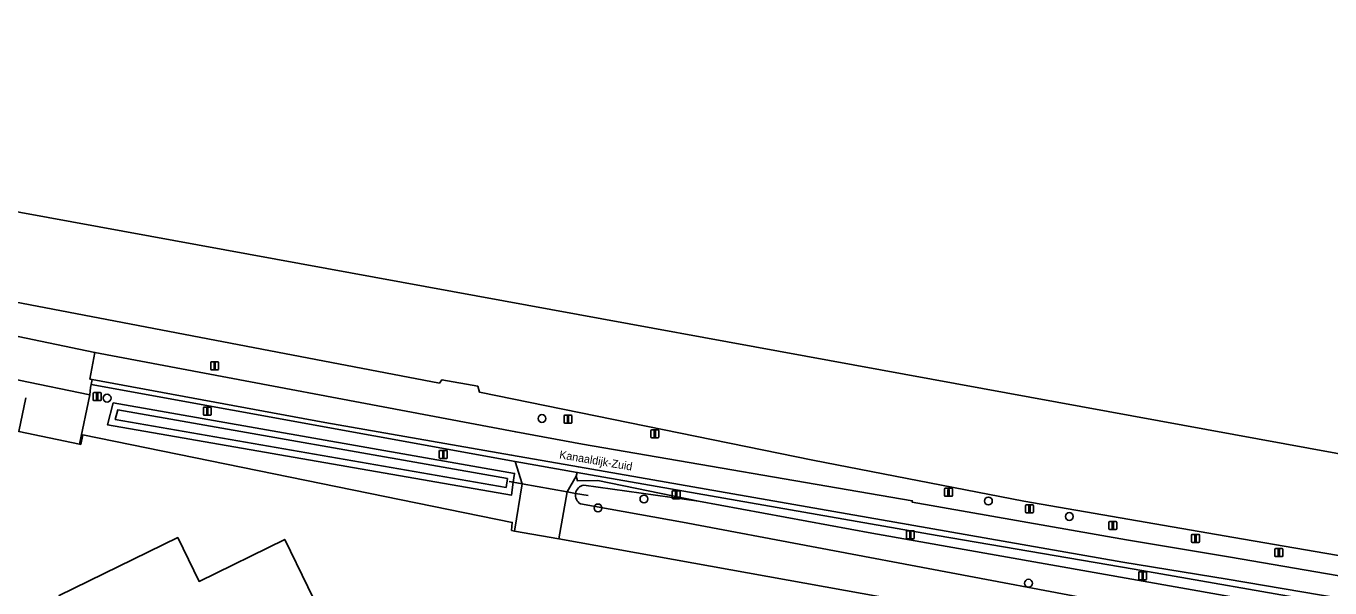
# Model space of a CAD drawing. Extents: x 163043 to 165076, y 382019 to 382874.
# Drawn here: x 163253.6 to 163416.5, y 382804 to 382874.2 of the extents above; entities that cross this region are included whole.
import ezdxf

# ---------------------------------------------------------------- set-up
doc = ezdxf.new("R2010")
doc.units = 0
for name, color, linetype in [('IMGEO_Afsluitpaal', 7, 'Continuous'), ('IMGEO_Boom', 7, 'Continuous'), ('IMGEO_Duiker', 7, 'Continuous'), ('IMGEO_Erf', 7, 'Continuous'), ('IMGEO_Fietspad_gesloten', 7, 'Continuous'), ('IMGEO_Groenvoorziening', 7, 'Continuous'), ('IMGEO_Hek', 7, 'Continuous'), ('IMGEO_Lichtmast', 7, 'Continuous'), ('IMGEO_Oever', 7, 'Continuous'), ('IMGEO_Openbare_ruimte_label', 7, 'Continuous'), ('IMGEO_Pand', 7, 'Continuous'), ('IMGEO_Rijbaan_lokaal_halfverhard', 7, 'Continuous'), ('IMGEO_Rijbaan_lokaal_open', 7, 'Continuous'), ('IMGEO_Verkeersbordpaal', 7, 'Continuous'), ('IMGEO_Voetpad_open', 7, 'Continuous'), ('IMGEO_Waterloop', 7, 'Continuous')]:
    doc.layers.add(name, color=color, linetype=linetype)

msp = doc.modelspace()

# ---------------------------------------------------------------- linework, layer by layer
at = {"layer": 'IMGEO_Afsluitpaal'}
for p, q in [((163320.83, 382824.69), (163320.83, 382825.49)), ((163320.83, 382825.49), (163320.83, 382824.69)), ((163320.93, 382825.59), (163321.72, 382825.59)), ((163321.72, 382825.59), (163320.93, 382825.59)), ((163321.72, 382824.59), (163320.93, 382824.59)), ((163320.93, 382824.59), (163321.72, 382824.59)), ((163321.82, 382825.49), (163321.82, 382824.69)), ((163321.82, 382824.69), (163321.82, 382825.49)), ((163331.68, 382822.85), (163331.68, 382823.65)), ((163331.68, 382823.65), (163331.68, 382822.85)), ((163331.78, 382823.75), (163332.57, 382823.75)), ((163332.57, 382823.75), (163331.78, 382823.75)), ((163332.57, 382822.75), (163331.78, 382822.75)), ((163331.78, 382822.75), (163332.57, 382822.75)), ((163332.67, 382823.65), (163332.67, 382822.85)), ((163332.67, 382822.85), (163332.67, 382823.65)), ((163368.38, 382815.54), (163368.38, 382816.34)), ((163368.38, 382816.34), (163368.38, 382815.54)), ((163368.48, 382816.44), (163369.27, 382816.44)), ((163369.27, 382816.44), (163368.48, 382816.44)), ((163369.37, 382816.34), (163369.37, 382815.54)), ((163369.37, 382815.54), (163369.37, 382816.34)), ((163369.27, 382815.44), (163368.48, 382815.44)), ((163368.48, 382815.44), (163369.27, 382815.44)), ((163378.5, 382813.47), (163378.5, 382814.27)), ((163378.5, 382814.27), (163378.5, 382813.47)), ((163378.6, 382814.37), (163379.39, 382814.37)), ((163379.39, 382814.37), (163378.6, 382814.37)), ((163379.49, 382814.27), (163379.49, 382813.47)), ((163379.49, 382813.47), (163379.49, 382814.27)), ((163379.39, 382813.37), (163378.6, 382813.37)), ((163378.6, 382813.37), (163379.39, 382813.37)), ((163388.91, 382811.4), (163388.91, 382812.2)), ((163388.91, 382812.2), (163388.91, 382811.4)), ((163389.01, 382812.3), (163389.8, 382812.3)), ((163389.8, 382812.3), (163389.01, 382812.3)), ((163389.8, 382811.3), (163389.01, 382811.3)), ((163389.01, 382811.3), (163389.8, 382811.3)), ((163389.9, 382812.2), (163389.9, 382811.4)), ((163389.9, 382811.4), (163389.9, 382812.2)), ((163399.25, 382809.78), (163399.25, 382810.58)), ((163399.25, 382810.58), (163399.25, 382809.78)), ((163399.35, 382810.68), (163400.14, 382810.68)), ((163400.14, 382810.68), (163399.35, 382810.68)), ((163400.14, 382809.68), (163399.35, 382809.68)), ((163399.35, 382809.68), (163400.14, 382809.68)), ((163400.24, 382810.58), (163400.24, 382809.78)), ((163400.24, 382809.78), (163400.24, 382810.58)), ((163409.66, 382808.01), (163409.66, 382808.8)), ((163409.66, 382808.8), (163409.66, 382808.01)), ((163409.76, 382808.9), (163410.55, 382808.9)), ((163410.55, 382808.9), (163409.76, 382808.9)), ((163410.55, 382807.91), (163409.76, 382807.91)), ((163409.76, 382807.91), (163410.55, 382807.91)), ((163410.65, 382808.8), (163410.65, 382808.01)), ((163410.65, 382808.01), (163410.65, 382808.8))]:
    msp.add_line(p, q, dxfattribs=at)
for points in [[(163321.25, 382825.47), (163321.4, 382825.47), (163321.4, 382824.72), (163321.25, 382824.72), (163321.25, 382825.47)], [(163332.1, 382823.62), (163332.25, 382823.62), (163332.25, 382822.87), (163332.1, 382822.87), (163332.1, 382823.62)], [(163368.8, 382816.31), (163368.95, 382816.31), (163368.95, 382815.56), (163368.8, 382815.56), (163368.8, 382816.31)], [(163378.92, 382814.24), (163379.07, 382814.24), (163379.07, 382813.49), (163378.92, 382813.49), (163378.92, 382814.24)], [(163389.33, 382812.18), (163389.48, 382812.18), (163389.48, 382811.43), (163389.33, 382811.43), (163389.33, 382812.18)], [(163399.67, 382810.55), (163399.82, 382810.55), (163399.82, 382809.8), (163399.67, 382809.8), (163399.67, 382810.55)], [(163410.08, 382808.78), (163410.23, 382808.78), (163410.23, 382808.03), (163410.08, 382808.03), (163410.08, 382808.78)]]:
    msp.add_lwpolyline(points, dxfattribs=at)
for centre, start, end in [((163320.93, 382825.49), 90, 180), ((163320.93, 382825.49), 90, 180), ((163320.93, 382824.69), 180, 270), ((163320.93, 382824.69), 180, 270), ((163321.72, 382825.49), 0, 90), ((163321.72, 382825.49), 360, 90), ((163321.72, 382824.69), 270, 0), ((163321.72, 382824.69), 270, 0), ((163331.78, 382823.65), 90, 180), ((163331.78, 382823.65), 90, 180), ((163331.78, 382822.85), 180, 270), ((163331.78, 382822.85), 180, 270), ((163332.57, 382823.65), 0, 90), ((163332.57, 382823.65), 360, 90), ((163332.57, 382822.85), 270, 0), ((163332.57, 382822.85), 270, 0), ((163368.48, 382816.34), 90, 180), ((163368.48, 382816.34), 90, 180), ((163369.27, 382816.34), 0, 90), ((163369.27, 382816.34), 360, 90), ((163368.48, 382815.54), 180, 270), ((163368.48, 382815.54), 180, 270), ((163369.27, 382815.54), 270, 0), ((163369.27, 382815.54), 270, 0), ((163378.6, 382814.27), 90, 180), ((163378.6, 382814.27), 90, 180), ((163379.39, 382814.27), 0, 90), ((163379.39, 382814.27), 360, 90), ((163378.6, 382813.47), 180, 270), ((163378.6, 382813.47), 180, 270), ((163379.39, 382813.47), 270, 0), ((163379.39, 382813.47), 270, 0), ((163389.01, 382812.2), 90, 180), ((163389.01, 382812.2), 90, 180), ((163389.01, 382811.4), 180, 270), ((163389.01, 382811.4), 180, 270), ((163389.8, 382812.2), 0, 90), ((163389.8, 382812.2), 360, 90), ((163389.8, 382811.4), 270, 0), ((163389.8, 382811.4), 270, 0), ((163399.35, 382810.58), 90, 180), ((163399.35, 382810.58), 90, 180), ((163399.35, 382809.78), 180, 270), ((163399.35, 382809.78), 180, 270), ((163400.14, 382810.58), 0, 90), ((163400.14, 382810.58), 360, 90), ((163400.14, 382809.78), 270, 0), ((163400.14, 382809.78), 270, 0), ((163409.76, 382808.8), 90, 180), ((163409.76, 382808.8), 90, 180), ((163409.76, 382808.01), 180, 270), ((163409.76, 382808.01), 180, 270), ((163410.55, 382808.8), 0, 90), ((163410.55, 382808.8), 360, 90), ((163410.55, 382808.01), 270, 0), ((163410.55, 382808.01), 270, 0)]:
    msp.add_arc(centre, 0.1, start, end, dxfattribs=at)
at = {"layer": 'IMGEO_Boom'}
for centre in [(163263.72, 382827.71), (163318.07, 382825.16), (163325.07, 382813.99), (163330.81, 382815.11), (163373.86, 382814.85), (163383.98, 382812.92), (163378.87, 382804.58)]:
    msp.add_circle(centre, 0.489, dxfattribs=at)
at = {"layer": 'IMGEO_Duiker'}
msp.add_lwpolyline([(163313.96, 382817.31), (163314.48, 382817.22), (163315.59, 382817.02), (163321.22, 382816), (163322.27, 382815.81), (163323.84, 382815.53)], dxfattribs=at)
at = {"layer": 'IMGEO_Erf'}
msp.add_lwpolyline([(163360.61, 382802.83), (163320.19, 382810.11), (163314.65, 382811.1), (163314.26, 382811.17), (163314.35, 382812.18), (163260.67, 382823.11), (163260.43, 382821.93), (163260.28, 382821.96), (163252.7, 382823.52), (163242.43, 382825.65), (163242.33, 382825.25), (163240, 382825.68), (163241.32, 382832.3), (163232.1, 382834.21), (163234.48, 382827.11), (163183.14, 382837.73), (163182.27, 382837.91), (163182.21, 382837.62), (163181.79, 382837.7), (163171.55, 382795.71), (163170.41, 382791.08), (163170.29, 382791.11)], dxfattribs=at)
msp.add_lwpolyline([(163260.37, 382797.58), (163257.72, 382803.04), (163272.56, 382810.28), (163275.22, 382804.81), (163285.92, 382810.05), (163288.8, 382804.14), (163299.84, 382781.52), (163300.53, 382780.1), (163259.8, 382760.22), (163255.22, 382757.98), (163249.59, 382769.57), (163247.16, 382774.53), (163251.73, 382776.78), (163245.19, 382790.17)], close=True, dxfattribs=at)
at = {"layer": 'IMGEO_Fietspad_gesloten'}
msp.add_lwpolyline([(163600.16, 382778.49), (163481.75, 382795.75), (163452.39, 382800.23), (163452.38, 382800.08), (163422.79, 382804.65), (163404.12, 382807.82), (163391.13, 382810.02), (163364.32, 382814.73), (163364.34, 382814.88), (163323.12, 382821.97), (163314.79, 382823.48), (163262.2, 382833.43), (163261.58, 382830.1), (163261.84, 382830.05), (163290.92, 382824.68), (163314.27, 382820.6), (163322.62, 382819.12), (163363.84, 382811.92), (163390.65, 382807.22), (163403.68, 382805.1), (163422.35, 382801.94), (163481.33, 382792.88), (163658.89, 382766.97)], dxfattribs=at)
at = {"layer": 'IMGEO_Groenvoorziening'}
for points in [[(163550.36, 382788.13), (163500, 382795.74), (163484.72, 382798.05), (163441.72, 382804), (163423.67, 382806.99), (163404.52, 382810.31), (163378.29, 382814.85), (163351.91, 382819.96), (163310.24, 382828.46), (163310.04, 382829.2), (163305.57, 382830.01), (163305.26, 382829.6), (163197.03, 382850.28), (163181.62, 382853.49), (163181.59, 382853.34), (163179.29, 382853.86), (163178.87, 382852.1), (163177.11, 382852.51), (163177.52, 382854.26), (163169.89, 382855.92), (163169.23, 382852.93)], [(163170.92, 382852.45), (163262.2, 382833.43), (163314.79, 382823.48), (163323.12, 382821.97), (163364.34, 382814.88), (163364.32, 382814.73), (163391.13, 382810.02), (163404.12, 382807.82), (163422.79, 382804.65), (163452.38, 382800.08), (163452.39, 382800.23), (163481.75, 382795.75), (163600.16, 382778.49)], [(163323.3, 382816.84), (163337.61, 382814.84), (163325.03, 382817.42), (163322.49, 382817.39), (163322.36, 382817.94), (163321.22, 382816), (163320.19, 382810.11), (163360.61, 382802.83), (163359.37, 382797.83), (163374.85, 382798.03), (163401.89, 382794.15), (163410.94, 382792.85), (163500, 382779.47), (163535.41, 382774.6)], [(163535.08, 382784.39), (163477.86, 382792.74), (163437.86, 382798.77), (163416.38, 382802.09), (163392.06, 382806.33), (163367.47, 382810.55), (163322.47, 382818.43), (163322.36, 382817.94), (163322.49, 382817.39), (163325.03, 382817.42), (163337.61, 382814.84), (163359.3, 382810.82), (163403.34, 382803.03), (163422.96, 382799.57), (163500, 382787.56), (163548.66, 382779.98)], [(163901.57, 382725.6), (163891.58, 382726.84), (163814.14, 382738.31), (163792.78, 382741.61), (163745.19, 382750), (163693.63, 382755.7), (163644.4, 382763.31), (163599.03, 382769.82), (163550.48, 382777.74), (163531.31, 382780.73), (163500, 382785.31), (163403.56, 382799.39), (163402.77, 382799.54), (163335.61, 382812.21), (163322.88, 382814.5)]]:
    msp.add_lwpolyline(points, dxfattribs=at)
for points in [[(163261.73, 382829.42), (163261.65, 382829.02), (163261.55, 382828.14), (163260.28, 382821.96), (163260.43, 382821.93), (163260.67, 382823.11), (163314.35, 382812.18), (163314.26, 382811.17), (163314.65, 382811.1), (163315.59, 382817.02), (163314.71, 382819.8)], [(163264.46, 382827.14), (163314.64, 382818.3), (163314.48, 382817.22), (163314.26, 382815.6), (163263.75, 382824.38)]]:
    msp.add_lwpolyline(points, close=True, dxfattribs=at)
for start, end in [(100.1063, 170.0054), (169.9597, 239.7064)]:
    msp.add_arc((163323.52, 382815.59), 1.27, start, end, dxfattribs=at)
at = {"layer": 'IMGEO_Hek'}
for points in [[(163260.28, 382821.96), (163260.43, 382821.93), (163260.67, 382823.11), (163314.35, 382812.18), (163314.26, 382811.17), (163314.65, 382811.1)], [(163314.65, 382811.1), (163320.19, 382810.11)], [(163320.19, 382810.11), (163360.61, 382802.83), (163359.37, 382797.83)]]:
    msp.add_lwpolyline(points, dxfattribs=at)
at = {"layer": 'IMGEO_Lichtmast'}
for p, q in [((163275.75, 382825.68), (163275.75, 382826.48)), ((163275.75, 382826.48), (163275.75, 382825.68)), ((163275.85, 382826.58), (163276.64, 382826.58)), ((163276.64, 382826.58), (163275.85, 382826.58)), ((163276.74, 382826.48), (163276.74, 382825.68)), ((163276.74, 382825.68), (163276.74, 382826.48)), ((163276.64, 382825.58), (163275.85, 382825.58)), ((163275.85, 382825.58), (163276.64, 382825.58)), ((163305.24, 382820.28), (163305.24, 382821.08)), ((163305.24, 382821.08), (163305.24, 382820.28)), ((163305.34, 382821.18), (163306.13, 382821.18)), ((163306.13, 382821.18), (163305.34, 382821.18)), ((163306.23, 382821.08), (163306.23, 382820.28)), ((163306.23, 382820.28), (163306.23, 382821.08)), ((163306.13, 382820.18), (163305.34, 382820.18)), ((163305.34, 382820.18), (163306.13, 382820.18)), ((163334.34, 382815.24), (163334.34, 382816.04)), ((163334.34, 382816.04), (163334.34, 382815.24)), ((163334.44, 382816.14), (163335.23, 382816.14)), ((163335.23, 382816.14), (163334.44, 382816.14)), ((163335.33, 382816.04), (163335.33, 382815.24)), ((163335.33, 382815.24), (163335.33, 382816.04)), ((163335.23, 382815.14), (163334.44, 382815.14)), ((163334.44, 382815.14), (163335.23, 382815.14)), ((163363.61, 382810.24), (163363.61, 382811.04)), ((163363.61, 382811.04), (163363.61, 382810.24)), ((163363.71, 382811.14), (163364.5, 382811.14)), ((163364.5, 382811.14), (163363.71, 382811.14)), ((163364.6, 382811.04), (163364.6, 382810.24)), ((163364.6, 382810.24), (163364.6, 382811.04)), ((163364.5, 382810.14), (163363.71, 382810.14)), ((163363.71, 382810.14), (163364.5, 382810.14)), ((163392.64, 382805.12), (163392.64, 382805.92)), ((163392.64, 382805.92), (163392.64, 382805.12)), ((163392.74, 382806.02), (163393.53, 382806.02)), ((163393.53, 382806.02), (163392.74, 382806.02)), ((163393.53, 382805.02), (163392.74, 382805.02)), ((163392.74, 382805.02), (163393.53, 382805.02)), ((163393.63, 382805.92), (163393.63, 382805.12)), ((163393.63, 382805.12), (163393.63, 382805.92))]:
    msp.add_line(p, q, dxfattribs=at)
for points in [[(163276.17, 382826.46), (163276.32, 382826.46), (163276.32, 382825.71), (163276.17, 382825.71), (163276.17, 382826.46)], [(163305.66, 382821.06), (163305.81, 382821.06), (163305.81, 382820.31), (163305.66, 382820.31), (163305.66, 382821.06)], [(163334.76, 382816.02), (163334.91, 382816.02), (163334.91, 382815.27), (163334.76, 382815.27), (163334.76, 382816.02)], [(163364.03, 382811.01), (163364.18, 382811.01), (163364.18, 382810.26), (163364.03, 382810.26), (163364.03, 382811.01)], [(163393.06, 382805.9), (163393.21, 382805.9), (163393.21, 382805.15), (163393.06, 382805.15), (163393.06, 382805.9)]]:
    msp.add_lwpolyline(points, dxfattribs=at)
for centre, start, end in [((163275.85, 382826.48), 90, 180), ((163275.85, 382826.48), 90, 180), ((163275.85, 382825.68), 180, 270), ((163275.85, 382825.68), 180, 270), ((163276.64, 382826.48), 0, 90), ((163276.64, 382826.48), 360, 90), ((163276.64, 382825.68), 270, 0), ((163276.64, 382825.68), 270, 0), ((163305.34, 382821.08), 90, 180), ((163305.34, 382821.08), 90, 180), ((163306.13, 382821.08), 0, 90), ((163306.13, 382821.08), 360, 90), ((163305.34, 382820.28), 180, 270), ((163305.34, 382820.28), 180, 270), ((163306.13, 382820.28), 270, 0), ((163306.13, 382820.28), 270, 0), ((163334.44, 382816.04), 90, 180), ((163334.44, 382816.04), 90, 180), ((163335.23, 382816.04), 0, 90), ((163335.23, 382816.04), 360, 90), ((163334.44, 382815.24), 180, 270), ((163334.44, 382815.24), 180, 270), ((163335.23, 382815.24), 270, 0), ((163335.23, 382815.24), 270, 0), ((163363.71, 382811.04), 90, 180), ((163363.71, 382811.04), 90, 180), ((163364.5, 382811.04), 0, 90), ((163364.5, 382811.04), 360, 90), ((163363.71, 382810.24), 180, 270), ((163363.71, 382810.24), 180, 270), ((163364.5, 382810.24), 270, 0), ((163364.5, 382810.24), 270, 0), ((163392.74, 382805.92), 90, 180), ((163392.74, 382805.92), 90, 180), ((163392.74, 382805.12), 180, 270), ((163392.74, 382805.12), 180, 270), ((163393.53, 382805.92), 0, 90), ((163393.53, 382805.92), 360, 90), ((163393.53, 382805.12), 270, 0), ((163393.53, 382805.12), 270, 0)]:
    msp.add_arc(centre, 0.1, start, end, dxfattribs=at)
at = {"layer": 'IMGEO_Oever'}
for points in [[(163264.46, 382827.14), (163263.75, 382824.38), (163314.26, 382815.6), (163314.48, 382817.22), (163314.64, 382818.3)], [(163313.58, 382816.53), (163264.74, 382825.02), (163265.05, 382826.23), (163313.74, 382817.65)]]:
    msp.add_lwpolyline(points, close=True, dxfattribs=at)
at = {"layer": 'IMGEO_Pand'}
msp.add_lwpolyline([(163249.59, 382769.57), (163255.22, 382757.98), (163259.8, 382760.22), (163300.53, 382780.1), (163299.84, 382781.52), (163288.8, 382804.14), (163285.92, 382810.05), (163275.22, 382804.81), (163272.56, 382810.28), (163257.72, 382803.04), (163260.37, 382797.58), (163245.19, 382790.17), (163251.73, 382776.78), (163247.16, 382774.53)], close=True, dxfattribs=at)
at = {"layer": 'IMGEO_Rijbaan_lokaal_halfverhard'}
msp.add_lwpolyline([(163658.89, 382766.97), (163481.33, 382792.88), (163422.35, 382801.94), (163403.68, 382805.1), (163390.65, 382807.22), (163363.84, 382811.92), (163322.62, 382819.12), (163314.27, 382820.6), (163290.92, 382824.68), (163261.84, 382830.05), (163261.73, 382829.42), (163314.71, 382819.8), (163322.47, 382818.43), (163367.47, 382810.55), (163392.06, 382806.33), (163416.38, 382802.09), (163437.86, 382798.77), (163477.86, 382792.74), (163535.08, 382784.39)], dxfattribs=at)
at = {"layer": 'IMGEO_Rijbaan_lokaal_open'}
msp.add_lwpolyline([(163167.53, 382847.36), (163168.9, 382847.14), (163173.42, 382846.23), (163183.69, 382844.16), (163184.56, 382843.98), (163188.58, 382843.18), (163232.1, 382834.21), (163241.32, 382832.3), (163252.7, 382829.96), (163261.55, 382828.14), (163261.65, 382829.02), (163261.73, 382829.42), (163261.84, 382830.05), (163261.58, 382830.1), (163262.2, 382833.43), (163170.92, 382852.45)], dxfattribs=at)
at = {"layer": 'IMGEO_Verkeersbordpaal'}
for p, q in [((163276.77, 382832.24), (163277.56, 382832.24)), ((163277.56, 382832.24), (163276.77, 382832.24)), ((163276.67, 382831.34), (163276.67, 382832.14)), ((163276.67, 382832.14), (163276.67, 382831.34)), ((163277.56, 382831.24), (163276.77, 382831.24)), ((163276.77, 382831.24), (163277.56, 382831.24)), ((163277.66, 382832.14), (163277.66, 382831.34)), ((163277.66, 382831.34), (163277.66, 382832.14)), ((163261.98, 382827.5), (163261.98, 382828.3)), ((163261.98, 382828.3), (163261.98, 382827.5)), ((163262.08, 382828.4), (163262.87, 382828.4)), ((163262.87, 382828.4), (163262.08, 382828.4)), ((163262.87, 382827.4), (163262.08, 382827.4)), ((163262.08, 382827.4), (163262.87, 382827.4)), ((163262.97, 382828.3), (163262.97, 382827.5)), ((163262.97, 382827.5), (163262.97, 382828.3))]:
    msp.add_line(p, q, dxfattribs=at)
for points in [[(163277.09, 382832.11), (163277.24, 382832.11), (163277.24, 382831.36), (163277.09, 382831.36), (163277.09, 382832.11)], [(163262.4, 382828.27), (163262.55, 382828.27), (163262.55, 382827.52), (163262.4, 382827.52), (163262.4, 382828.27)]]:
    msp.add_lwpolyline(points, dxfattribs=at)
for centre, start, end in [((163276.77, 382832.14), 90, 180), ((163276.77, 382832.14), 90, 180), ((163277.56, 382832.14), 0, 90), ((163277.56, 382832.14), 360, 90), ((163276.77, 382831.34), 180, 270), ((163276.77, 382831.34), 180, 270), ((163277.56, 382831.34), 270, 0), ((163277.56, 382831.34), 270, 0), ((163262.08, 382828.3), 90, 180), ((163262.08, 382828.3), 90, 180), ((163262.08, 382827.5), 180, 270), ((163262.08, 382827.5), 180, 270), ((163262.87, 382828.3), 0, 90), ((163262.87, 382828.3), 360, 90), ((163262.87, 382827.5), 270, 0), ((163262.87, 382827.5), 270, 0)]:
    msp.add_arc(centre, 0.1, start, end, dxfattribs=at)
at = {"layer": 'IMGEO_Voetpad_open'}
msp.add_lwpolyline([(163253.56, 382827.74), (163252.7, 382823.52), (163260.28, 382821.96), (163261.55, 382828.14), (163252.7, 382829.96)], dxfattribs=at)
msp.add_lwpolyline([(163322.36, 382817.94), (163322.47, 382818.43), (163314.71, 382819.8), (163315.59, 382817.02), (163314.65, 382811.1), (163320.19, 382810.11), (163321.22, 382816)], close=True, dxfattribs=at)
at = {"layer": 'IMGEO_Waterloop'}
for points in [[(163123.71, 382866.34), (163125.44, 382874.2), (163542.42, 382797.92), (163683.11, 382777.18), (164147.9, 382708.69), (165075.56, 382573.63)], [(163550.36, 382788.13), (163500, 382795.74), (163484.72, 382798.05), (163441.72, 382804), (163423.67, 382806.99), (163404.52, 382810.31), (163378.29, 382814.85), (163351.91, 382819.96), (163310.24, 382828.46), (163310.04, 382829.2), (163305.57, 382830.01), (163305.26, 382829.6), (163197.03, 382850.28)], [(163961.29, 382721.23), (163941.47, 382723.93), (163892.47, 382731.14), (163843.66, 382737.95), (163793.38, 382745.36), (163780.57, 382747.06), (163759.96, 382750), (163694.14, 382759.99), (163692, 382760.32), (163599.59, 382773.47), (163558.31, 382778.65), (163548.66, 382779.98), (163500, 382787.56), (163422.96, 382799.57), (163403.34, 382803.03), (163359.3, 382810.82), (163337.61, 382814.84), (163323.3, 382816.84)], [(163322.88, 382814.5), (163335.61, 382812.21), (163402.77, 382799.54), (163403.56, 382799.39), (163500, 382785.31), (163531.31, 382780.73), (163550.48, 382777.74), (163599.03, 382769.82), (163644.4, 382763.31), (163693.63, 382755.7), (163745.19, 382750), (163792.78, 382741.61), (163814.14, 382738.31), (163891.58, 382726.84), (163901.57, 382725.6), (163960.72, 382718.96)]]:
    msp.add_lwpolyline(points, dxfattribs=at)
msp.add_lwpolyline([(163313.58, 382816.53), (163313.74, 382817.65), (163265.05, 382826.23), (163264.74, 382825.02)], close=True, dxfattribs=at)
for start, end in [(100.1063, 170.0054), (169.9597, 239.7064)]:
    msp.add_arc((163323.52, 382815.59), 1.27, start, end, dxfattribs=at)

# ---------------------------------------------------------------- texts
at = {"layer": 'IMGEO_Openbare_ruimte_label'}
msp.add_text('Kanaaldijk-Zuid', height=1, rotation=350.387, dxfattribs=at).set_placement((163320.18, 382820.19))

doc.saveas('drawing.dxf')
